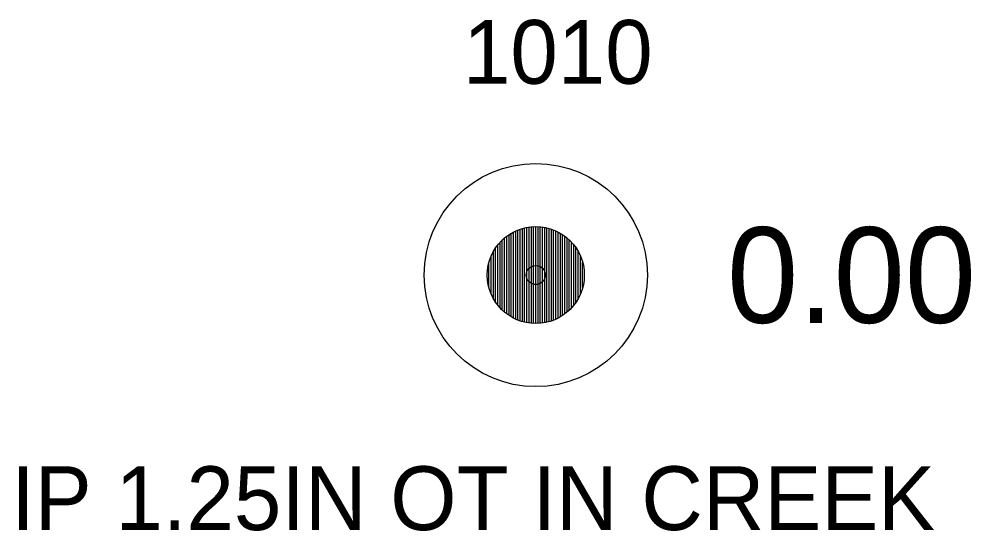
# Model space of a CAD drawing. Extents: x 1611865 to 1617004, y 775289 to 778546.
# Drawn here: x 1614701.69 to 1614716.62, y 778538.25 to 778546.28 of the extents above; entities that cross this region are included whole.
import ezdxf

# ---------------------------------------------------------------- set-up
doc = ezdxf.new("R2010")
doc.units = 0
for name, color, linetype in [('RD_EX_DV_Prop_txCode', 7, 'Continuous'), ('RD_EX_DV_PropPin', 7, 'Continuous'), ('RD_EX_TX_DV_Prop_ELEV', 7, 'Continuous'), ('RD_SMD_Locator', 7, 'Continuous')]:
    doc.layers.add(name, color=color, linetype=linetype)

msp = doc.modelspace()

# ---------------------------------------------------------------- linework, layer by layer
at = {"layer": 'RD_EX_DV_PropPin'}
for p, q in [((1614709.407, 778541.608), (1614709.407, 778542.921)), ((1614709.442, 778541.589), (1614709.442, 778542.94)), ((1614709.477, 778541.572), (1614709.477, 778542.957)), ((1614709.512, 778541.557), (1614709.512, 778542.972)), ((1614709.547, 778541.544), (1614709.547, 778542.985)), ((1614709.582, 778541.533), (1614709.582, 778542.996)), ((1614709.617, 778541.524), (1614709.617, 778543.005)), ((1614709.652, 778541.516), (1614709.652, 778543.012)), ((1614709.687, 778541.511), (1614709.687, 778543.018)), ((1614709.722, 778541.507), (1614709.722, 778543.022)), ((1614709.757, 778541.504), (1614709.757, 778543.025)), ((1614709.792, 778541.503), (1614709.792, 778543.025)), ((1614709.827, 778541.504), (1614709.827, 778543.025)), ((1614709.862, 778541.507), (1614709.862, 778543.022)), ((1614709.897, 778541.511), (1614709.897, 778543.018)), ((1614709.932, 778541.516), (1614709.932, 778543.012)), ((1614709.967, 778541.524), (1614709.967, 778543.005)), ((1614710.002, 778541.533), (1614710.002, 778542.996)), ((1614710.037, 778541.544), (1614710.037, 778542.985)), ((1614710.072, 778541.557), (1614710.072, 778542.972)), ((1614710.107, 778541.572), (1614710.107, 778542.957)), ((1614710.142, 778541.589), (1614710.142, 778542.94)), ((1614710.177, 778541.608), (1614710.177, 778542.921)), ((1614709.231, 778541.749), (1614709.231, 778542.779)), ((1614709.266, 778541.714), (1614709.266, 778542.815)), ((1614709.301, 778541.682), (1614709.301, 778542.847)), ((1614709.336, 778541.655), (1614709.336, 778542.874)), ((1614709.372, 778541.63), (1614709.372, 778542.899)), ((1614710.212, 778541.63), (1614710.212, 778542.899)), ((1614710.247, 778541.655), (1614710.247, 778542.874)), ((1614710.282, 778541.682), (1614710.282, 778542.847)), ((1614710.317, 778541.714), (1614710.317, 778542.815)), ((1614710.352, 778541.749), (1614710.352, 778542.779)), ((1614709.126, 778541.895), (1614709.126, 778542.634)), ((1614709.161, 778541.838), (1614709.161, 778542.691)), ((1614709.196, 778541.79), (1614709.196, 778542.739)), ((1614710.387, 778541.79), (1614710.387, 778542.739)), ((1614710.422, 778541.838), (1614710.422, 778542.691)), ((1614710.457, 778541.895), (1614710.457, 778542.634)), ((1614709.056, 778542.068), (1614709.056, 778542.461)), ((1614709.091, 778541.966), (1614709.091, 778542.562)), ((1614710.492, 778541.966), (1614710.492, 778542.562)), ((1614710.527, 778542.068), (1614710.527, 778542.461))]:
    msp.add_line(p, q, dxfattribs=at)
for radius in [1.75, 0.761]:
    msp.add_circle((1614709.792, 778542.264), radius, dxfattribs=at)
at = {"layer": 'RD_SMD_Locator'}
msp.add_circle((1614709.792, 778542.264), 0.15, dxfattribs=at)

# ---------------------------------------------------------------- texts
at = {"layer": 'RD_EX_DV_Prop_txCode'}
for s, p in [('1010', (1614708.65, 778545.264)), ('IP 1.25IN OT IN CREEK', (1614701.563, 778538.264))]:
    msp.add_text(s, height=1, dxfattribs=at).set_placement(p)
at = {"layer": 'RD_EX_TX_DV_Prop_ELEV'}
msp.add_text('0.00', height=1.5, dxfattribs=at).set_placement((1614712.792, 778541.514))

doc.saveas('drawing.dxf')
